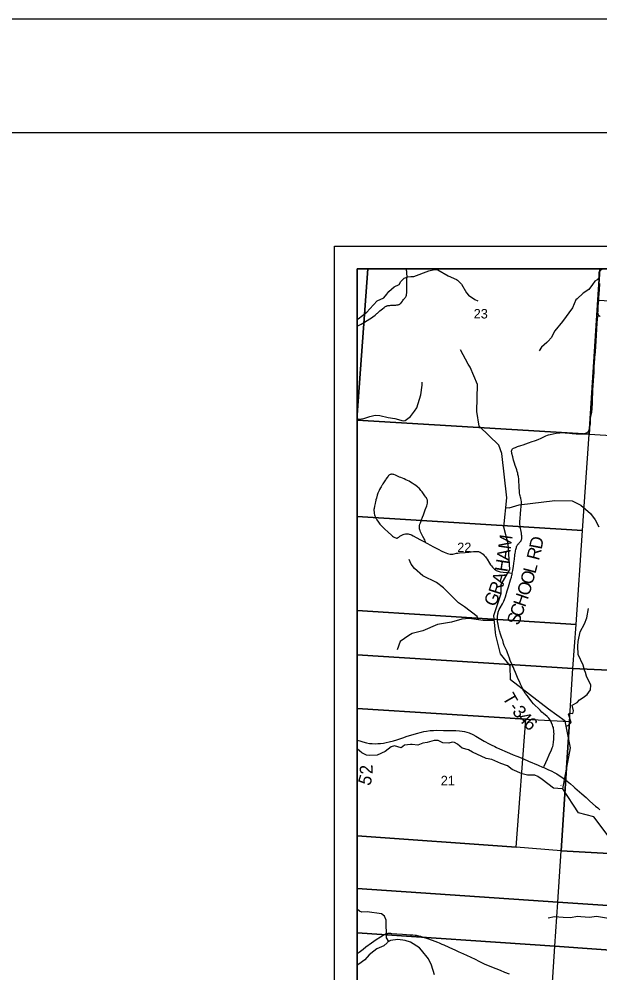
# Model space of a CAD drawing. Extents: x 0 to 34, y 0 to 22.
# Drawn here: x 22.027 to 24.586, y 17.797 to 22 of the extents above; entities that cross this region are included whole.
import ezdxf

# ---------------------------------------------------------------- set-up
doc = ezdxf.new("R2010")
doc.units = 0
for name, color, linetype in [('Default', 7, 'Continuous'), ('GM_X_County_Road', 7, 'Continuous'), ('GM_X_Minor_River', 7, 'Continuous'), ('GM_X_Section', 7, 'Continuous'), ('GM_X_Section_Text', 7, 'Continuous'), ('GM_X_State_Route', 7, 'Continuous'), ('GM_X_Township_Road', 7, 'Continuous'), ('GM_X_Township_Road_Text', 7, 'Continuous'), ('SH_Border', 7, 'Continuous'), ('SH_Cut_Line', 7, 'Continuous'), ('SH_Data', 7, 'Continuous'), ('SH_Text', 7, 'Continuous')]:
    doc.layers.add(name, color=color, linetype=linetype)

msp = doc.modelspace()

# ---------------------------------------------------------------- linework, layer by layer
at = {"layer": 'Default'}
for points in [[(23.5639, 20.9), (23.5167, 20.9), (23.5167, 20.2565)], [(23.5167, 20.2565), (23.5167, 20.233), (24.5388, 20.1708), (24.5856, 20.9), (23.5639, 20.9)], [(25.6226, 20.9), (24.5856, 20.9), (24.5388, 20.1708), (25.5703, 20.1097)], [(23.5167, 20.233), (23.5167, 19.8081), (24.5096, 19.7459), (24.5388, 20.1708)], [(23.5167, 19.8081), (23.5167, 19.3932), (24.4804, 19.3317), (24.5096, 19.7459)], [(23.5167, 19.3932), (23.5167, 19.1986), (24.4668, 19.1382), (24.4804, 19.3317)], [(23.5167, 19.1986), (23.5167, 18.962), (24.259, 18.9151), (24.4515, 18.9043), (24.4668, 19.1382)], [(23.5167, 18.962), (23.5167, 18.4005), (24.2171, 18.351), (24.259, 18.9151)], [(23.5167, 18.4005), (23.5167, 18.1686), (24.3998, 18.1092), (24.4145, 18.3347), (24.2171, 18.351)], [(23.5167, 18.1686), (23.5167, 17.973), (24.3871, 17.9146), (24.3998, 18.1092)], [(23.5167, 17.973), (23.5167, 17.5604), (24.3605, 17.505), (24.3871, 17.9146)]]:
    msp.add_lwpolyline(points, close=True, dxfattribs=at)
msp.add_lwpolyline([(27.7198, 20.9), (23.5167, 20.9), (23.5167, 16.1239), (23.5888, 16.1195), (25.0535, 16.0331), (25.3458, 16.0191), (26.0811, 15.9921), (26.3691, 15.9829), (26.8773, 15.953), (26.8866, 15.9536), (26.8953, 15.9537)], dxfattribs=at)
at = {"layer": 'GM_X_County_Road'}
for points in [[(24.5862, 20.6897), (24.5846, 20.6906), (24.5832, 20.6915), (24.5816, 20.693), (24.5804, 20.6944), (24.5789, 20.6969), (24.5782, 20.6985), (24.5776, 20.7002), (24.5774, 20.702), (24.5771, 20.7056), (24.5773, 20.7124), (24.5787, 20.7353), (24.5806, 20.7609), (24.5815, 20.7731), (24.5838, 20.8068), (24.5857, 20.8348)], [(23.5167, 17.8817), (23.5251, 17.8884), (23.5423, 17.9017), (23.5552, 17.9114), (23.5799, 17.9292), (23.6003, 17.9433), (23.6188, 17.9559), (23.6261, 17.9606), (23.632, 17.9643), (23.6365, 17.9667), (23.6391, 17.9679), (23.6415, 17.9688), (23.6452, 17.97), (23.6476, 17.9706), (23.6497, 17.9709), (23.6515, 17.9711), (23.6532, 17.9713), (23.6551, 17.9714), (23.6579, 17.9715), (23.659, 17.9715), (23.6636, 17.9713), (23.6671, 17.9711), (23.7161, 17.9679), (23.752, 17.9653), (23.761, 17.9645), (23.7717, 17.9634), (23.7761, 17.9627), (23.7811, 17.9618), (23.7884, 17.9601), (23.7956, 17.9581), (23.8028, 17.9559), (23.8257, 17.948), (23.8462, 17.9407), (23.8708, 17.9319), (23.8771, 17.9295), (23.8835, 17.9268), (23.8899, 17.924), (23.8977, 17.9204), (23.9202, 17.9099), (23.9502, 17.8963), (23.9641, 17.8899), (23.9722, 17.8862), (23.9974, 17.8748), (24.0165, 17.866), (24.0364, 17.8569), (24.053, 17.8487), (24.0669, 17.8417), (24.0765, 17.8373), (24.0941, 17.8297), (24.1278, 17.8158), (24.1458, 17.8085), (24.1653, 17.8003), (24.1861, 17.7921)]]:
    msp.add_lwpolyline(points, dxfattribs=at)
at = {"layer": 'GM_X_Minor_River'}
for points in [[(23.5167, 20.6785), (23.5205, 20.6796), (23.5588, 20.709), (23.5724, 20.7238), (23.605, 20.7581), (23.6331, 20.771), (23.6475, 20.7885), (23.6558, 20.7999), (23.6794, 20.8205), (23.701, 20.8308), (23.7089, 20.8437), (23.723, 20.8578), (23.7389, 20.8639), (23.7533, 20.8654), (23.7665, 20.8655), (23.8325, 20.8899), (23.8564, 20.896), (23.8719, 20.8952), (23.9174, 20.8687), (23.9542, 20.852), (23.9587, 20.8493), (23.9754, 20.8322), (23.9978, 20.7931), (24.0065, 20.7836), (24.0349, 20.7646), (24.0478, 20.7582)], [(24.6012, 20.9), (24.5899, 20.8956), (24.5812, 20.8846), (24.5808, 20.8599), (24.5732, 20.8511), (24.5626, 20.845), (24.5535, 20.831), (24.5372, 20.8089), (24.5118, 20.7921), (24.486, 20.7666), (24.4792, 20.7628), (24.4651, 20.7282), (24.4211, 20.6669), (24.3878, 20.6262), (24.3703, 20.595), (24.3574, 20.581), (24.3517, 20.5745), (24.3286, 20.5539), (24.3187, 20.5383)], [(24.6358, 18.3825), (24.5593, 18.4839), (24.4908, 18.5019), (24.4222, 18.6075), (24.4559, 18.7885), (24.4331, 18.9063), (24.3595, 18.9584), (24.1919, 19.0886), (24.1907, 19.1496), (24.1471, 19.2028), (24.1267, 19.2853), (24.1254, 19.2967), (24.1179, 19.3714), (24.1501, 19.4688), (24.1503, 19.509), (24.1885, 19.5747), (24.181, 19.6869), (24.1618, 19.7604), (24.176, 19.8899), (24.1541, 20.0852), (24.1411, 20.123), (24.0538, 20.2057), (24.0442, 20.2713), (24.0457, 20.389), (24.0139, 20.4654), (24.0046, 20.4797), (23.9712, 20.5432)], [(23.5167, 20.2402), (23.5237, 20.2375), (23.5453, 20.2394), (23.5726, 20.2489), (23.5958, 20.2547), (23.6166, 20.2536), (23.653, 20.2437), (23.6829, 20.2392), (23.7197, 20.2301), (23.7284, 20.2309), (23.7508, 20.2491), (23.7682, 20.2727), (23.7785, 20.2876), (23.7971, 20.3446), (23.8024, 20.3868), (23.8028, 20.3933), (23.8032, 20.3994)], [(24.1714, 19.8482), (24.1859, 19.8466), (24.2306, 19.8601), (24.3866, 19.8788), (24.4633, 19.8774), (24.5014, 19.8583), (24.5442, 19.8216), (24.5647, 19.794), (24.5809, 19.763)], [(24.051, 19.3533), (24.0454, 19.3667), (23.9894, 19.4104), (23.962, 19.4275), (23.896, 19.493), (23.8656, 19.5177), (23.8052, 19.5467), (23.7689, 19.5783), (23.7543, 19.5979), (23.7455, 19.6182)], [(24.4383, 18.8844), (24.4478, 18.8886), (24.4584, 18.9), (24.4467, 18.9376), (24.4516, 18.9418), (24.466, 18.9395), (24.4698, 18.9517), (24.4634, 18.976), (24.4854, 18.9882), (24.4952, 19.0004), (24.5119, 19.0107), (24.529, 19.0232), (24.5449, 19.0449), (24.5457, 19.0654), (24.5267, 19.1038), (24.5218, 19.1202), (24.5173, 19.1304), (24.5116, 19.1525), (24.4904, 19.2), (24.4881, 19.2361), (24.4904, 19.2566), (24.4984, 19.2996), (24.5185, 19.3349), (24.5283, 19.3619), (24.5356, 19.403)], [(24.1201, 19.3497), (24.0718, 19.3504), (24.0092, 19.3592), (23.9777, 19.3559), (23.9323, 19.342), (23.8706, 19.3322), (23.806, 19.3046), (23.758, 19.2927), (23.7434, 19.283), (23.7054, 19.257), (23.6928, 19.221)], [(24.085, 18.7418), (24.0244, 18.7691), (24.0065, 18.7805), (23.9793, 18.7877), (23.958, 18.8044), (23.9455, 18.8127), (23.9353, 18.8135), (23.9205, 18.8096), (23.8936, 18.8111), (23.8727, 18.8206), (23.8549, 18.821), (23.825, 18.8114), (23.806, 18.8099), (23.7829, 18.8007), (23.7579, 18.8026), (23.7514, 18.8037), (23.7245, 18.8003), (23.7109, 18.7885), (23.6809, 18.7968), (23.6665, 18.793), (23.6396, 18.7724), (23.6043, 18.7561), (23.5721, 18.7553), (23.5581, 18.7556), (23.5373, 18.7659), (23.5167, 18.7845)], [(24.42, 18.6081), (24.3814, 18.6102), (24.331, 18.6485), (24.3116, 18.6626), (24.2995, 18.6675), (24.2673, 18.6679), (24.2434, 18.6743), (24.1991, 18.6929), (24.1779, 18.7096), (24.149, 18.7194), (24.1093, 18.7365), (24.085, 18.7418)], [(24.4132, 18.6247), (24.4144, 18.6225)], [(23.6562, 17.9355), (23.6458, 17.952), (23.6443, 18.0288), (23.6374, 18.047), (23.623, 18.0569), (23.5597, 18.0652), (23.5374, 18.0648), (23.5268, 18.0693), (23.5169, 18.0781), (23.5167, 18.0792)], [(25.0835, 17.7983), (25.0376, 17.8285), (25.0069, 17.8501), (24.9869, 17.8627), (24.9698, 17.8645), (24.9562, 17.8737), (24.9376, 17.8961), (24.8728, 17.9401), (24.8489, 17.9538), (24.7996, 17.9689), (24.7769, 17.9795), (24.7561, 18), (24.7284, 18.0107), (24.6954, 18.0239), (24.6461, 18.0322), (24.6416, 18.033), (24.5711, 18.0455), (24.54, 18.0409), (24.5021, 18.0446), (24.4869, 18.0457), (24.4562, 18.0396), (24.424, 18.0415), (24.3853, 18.0434), (24.3577, 18.0384)], [(23.8568, 17.7876), (23.8436, 17.831), (23.8299, 17.8587), (23.8, 17.8971), (23.7902, 17.9069), (23.7507, 17.9324), (23.7276, 17.9403), (23.695, 17.9445), (23.6628, 17.9391), (23.6503, 17.9322), (23.6492, 17.9288), (23.6344, 17.9155), (23.6037, 17.9033), (23.5904, 17.8923), (23.5695, 17.8759), (23.5506, 17.8549), (23.524, 17.8348), (23.5167, 17.8313)]]:
    msp.add_lwpolyline(points, dxfattribs=at)
at = {"layer": 'GM_X_Section'}
for points in [[(24.5388, 20.1708), (25.5703, 20.1097), (25.5433, 19.6923), (25.5164, 19.2759), (25.5041, 19.0909), (25.5038, 19.0874), (24.9075, 19.1174), (24.4668, 19.1382), (24.4804, 19.3317), (24.5096, 19.7459)], [(24.4668, 19.1382), (24.9075, 19.1174), (24.8626, 18.3102), (24.4145, 18.3347), (24.4515, 18.9043)], [(24.4515, 18.9043), (24.4145, 18.3347), (24.2171, 18.351), (24.259, 18.9151)], [(24.8626, 18.3102), (25.3836, 18.2803), (25.3665, 18.0434), (24.3998, 18.1092), (24.4145, 18.3347)], [(24.3998, 18.1092), (25.3665, 18.0434), (25.4369, 18.0387), (25.4267, 17.8394), (24.3871, 17.9146)], [(25.4267, 17.8394), (25.3999, 17.4262), (24.3605, 17.505), (24.3871, 17.9146)]]:
    msp.add_lwpolyline(points, close=True, dxfattribs=at)
at = {"layer": 'GM_X_State_Route'}
for points in [[(23.5167, 18.823), (23.5274, 18.819), (23.541, 18.8146), (23.5569, 18.8109), (23.5709, 18.8084), (23.5819, 18.8075), (23.5968, 18.8068), (23.6068, 18.807), (23.6187, 18.8077), (23.6317, 18.8092), (23.6446, 18.8115), (23.6579, 18.8145), (23.6759, 18.8196), (23.6908, 18.8242), (23.7214, 18.8345), (23.732, 18.8379), (23.7778, 18.8517), (23.7993, 18.8578), (23.8095, 18.8603), (23.8217, 18.8623), (23.8377, 18.8643), (23.8525, 18.8654), (23.868, 18.8659), (23.8966, 18.8657), (23.927, 18.8654), (23.9512, 18.8647), (23.9667, 18.8638), (23.979, 18.8624), (23.9887, 18.8607), (23.9988, 18.8581), (24.0099, 18.8543), (24.0254, 18.8479), (24.0385, 18.8403), (24.0616, 18.827), (24.0754, 18.8187), (24.0821, 18.8148), (24.0918, 18.8093), (24.1067, 18.8017), (24.1221, 18.7942), (24.13, 18.7906), (24.1439, 18.7845), (24.1768, 18.7702), (24.187, 18.7657), (24.2042, 18.7585), (24.2192, 18.7523), (24.2312, 18.7473), (24.2485, 18.7396), (24.2708, 18.7302), (24.3131, 18.7122), (24.3325, 18.704), (24.338, 18.7016), (24.3591, 18.692), (24.3709, 18.6866), (24.3865, 18.6788), (24.3956, 18.6737), (24.4067, 18.6669), (24.4176, 18.6598), (24.4297, 18.6512), (24.4415, 18.6421), (24.4492, 18.6358), (24.4558, 18.6302), (24.4692, 18.6184), (24.4759, 18.6125)], [(24.4759, 18.6125), (24.4856, 18.604), (24.5053, 18.5865), (24.5248, 18.5693), (24.5415, 18.5543), (24.5665, 18.5321), (24.5762, 18.5236), (24.5839, 18.5175), (24.586, 18.5156)]]:
    msp.add_lwpolyline(points, dxfattribs=at)
at = {"layer": 'GM_X_Township_Road'}
for points in [[(23.5167, 20.6466), (23.5187, 20.6476), (23.5346, 20.6561), (23.5482, 20.6637), (23.5605, 20.671), (23.572, 20.6785), (23.5802, 20.6841), (23.586, 20.6886), (23.5952, 20.6957), (23.5987, 20.6987), (23.6032, 20.7024), (23.6059, 20.7047), (23.6167, 20.7139), (23.6274, 20.7225), (23.6346, 20.7284), (23.6386, 20.7313), (23.6416, 20.7332), (23.6435, 20.7343), (23.6458, 20.7353), (23.6472, 20.7359), (23.649, 20.7364), (23.6513, 20.7371), (23.6533, 20.7376), (23.6556, 20.738), (23.6572, 20.7382), (23.6601, 20.7385), (23.6642, 20.7388), (23.6751, 20.7393), (23.6823, 20.7396), (23.6873, 20.7398), (23.6912, 20.7402), (23.6938, 20.7405), (23.6968, 20.7411), (23.6993, 20.742), (23.7015, 20.7429), (23.7036, 20.7442), (23.7066, 20.7466), (23.7079, 20.7478), (23.7111, 20.7514), (23.7158, 20.7573), (23.718, 20.7601), (23.721, 20.7637), (23.7266, 20.7705), (23.7284, 20.7728), (23.7296, 20.7743), (23.7308, 20.7765), (23.7317, 20.7787), (23.733, 20.7827), (23.7335, 20.7849), (23.7343, 20.7899), (23.7345, 20.7928), (23.7347, 20.798), (23.7347, 20.8002), (23.7346, 20.8073), (23.7352, 20.8337), (23.7358, 20.8572), (23.736, 20.8681), (23.7357, 20.8756), (23.7356, 20.8797), (23.7352, 20.8853), (23.7349, 20.888), (23.7342, 20.8926), (23.7338, 20.8959), (23.7332, 20.8989), (23.733, 20.9)], [(24.5806, 20.7609), (24.6039, 20.7593), (24.6237, 20.7583), (24.6678, 20.7556), (24.7203, 20.7527)], [(24.1973, 20.0991), (24.1977, 20.1006), (24.1983, 20.102), (24.1993, 20.1037), (24.2008, 20.1055), (24.2026, 20.107), (24.2052, 20.1086), (24.2092, 20.1105), (24.2143, 20.1128), (24.2232, 20.1159), (24.2367, 20.1203), (24.2479, 20.1241), (24.2712, 20.1326), (24.2874, 20.1382), (24.2969, 20.1412), (24.3068, 20.1447), (24.316, 20.1483), (24.3245, 20.1521), (24.3476, 20.1629), (24.3545, 20.1658), (24.3598, 20.1676), (24.367, 20.1694), (24.3796, 20.1722), (24.393, 20.1746), (24.4022, 20.1762), (24.4098, 20.1773), (24.4138, 20.1775), (24.417, 20.1776), (24.4232, 20.1775), (24.4332, 20.1768), (24.4511, 20.1752), (24.4629, 20.174), (24.4666, 20.1736), (24.4814, 20.1724), (24.4913, 20.1719), (24.4999, 20.172), (24.5073, 20.1723), (24.5123, 20.1728), (24.5177, 20.1737), (24.5225, 20.175), (24.5259, 20.1763), (24.5292, 20.1779), (24.5317, 20.1798), (24.5333, 20.1814), (24.5357, 20.1847), (24.5369, 20.1874), (24.5377, 20.1896), (24.5392, 20.1949), (24.5417, 20.2051), (24.5431, 20.2117), (24.5436, 20.2153), (24.5439, 20.22), (24.544, 20.225), (24.544, 20.2307), (24.544, 20.2332), (24.5442, 20.2356), (24.5444, 20.2385), (24.5449, 20.2415), (24.5464, 20.2487), (24.5476, 20.2549), (24.5486, 20.2606), (24.5497, 20.2685), (24.5512, 20.2818), (24.5519, 20.2928), (24.5524, 20.3008), (24.5527, 20.3112), (24.5531, 20.3229), (24.5536, 20.3359), (24.554, 20.3452), (24.5542, 20.3495), (24.5548, 20.3645), (24.5552, 20.3713), (24.5557, 20.3799), (24.5564, 20.3904), (24.5571, 20.4013), (24.5576, 20.4081), (24.5586, 20.4235), (24.5597, 20.4452), (24.5607, 20.4638), (24.5623, 20.4892), (24.5629, 20.4985), (24.5634, 20.5059), (24.5637, 20.5102), (24.5642, 20.5183), (24.5655, 20.535), (24.5688, 20.5802), (24.5724, 20.6348), (24.5742, 20.6583), (24.5756, 20.6801), (24.5762, 20.6858), (24.577, 20.6887), (24.5783, 20.691), (24.5804, 20.6944)], [(24.338, 18.7016), (24.3406, 18.708), (24.3471, 18.7234), (24.3545, 18.7405), (24.3619, 18.7576), (24.3717, 18.7791), (24.3758, 18.7888), (24.378, 18.7952), (24.3793, 18.8), (24.3802, 18.8048), (24.3809, 18.8109), (24.3822, 18.8295), (24.3832, 18.8425), (24.3835, 18.8505), (24.3833, 18.858), (24.3827, 18.866), (24.3819, 18.8721), (24.3806, 18.8775), (24.3787, 18.8833), (24.3764, 18.8891), (24.372, 18.8994), (24.3691, 18.9055), (24.3665, 18.9104), (24.3634, 18.915), (24.3604, 18.9189), (24.3571, 18.9225), (24.3526, 18.9267), (24.3368, 18.9399), (24.3303, 18.9456), (24.3218, 18.9539), (24.3131, 18.9627), (24.3006, 18.9757), (24.2938, 18.983), (24.2862, 18.992), (24.2702, 19.0127), (24.2648, 19.0195), (24.258, 19.0283), (24.2559, 19.0313), (24.2516, 19.0373), (24.2501, 19.0394), (24.2474, 19.0442), (24.2425, 19.0543), (24.2356, 19.0697), (24.231, 19.0803), (24.2262, 19.091), (24.2199, 19.1057), (24.2136, 19.1213), (24.2086, 19.1334), (24.2049, 19.1419), (24.201, 19.1503), (24.1986, 19.1554), (24.1934, 19.1667), (24.1903, 19.1741), (24.1867, 19.1834), (24.1825, 19.1951), (24.1783, 19.2072), (24.1751, 19.2154), (24.1684, 19.2301), (24.1645, 19.2393), (24.1614, 19.2487), (24.1573, 19.2624), (24.1538, 19.2723), (24.1509, 19.2805), (24.1483, 19.2888), (24.1439, 19.3037), (24.1408, 19.3163), (24.1393, 19.323), (24.1371, 19.3338), (24.1352, 19.3441), (24.1343, 19.3516), (24.134, 19.3561), (24.1339, 19.3614), (24.1346, 19.3688), (24.1356, 19.3769), (24.1361, 19.3793), (24.1368, 19.3828), (24.1377, 19.3859), (24.1389, 19.3907), (24.1403, 19.3944), (24.1422, 19.3976), (24.1465, 19.4049), (24.157, 19.4239), (24.1611, 19.4322), (24.1623, 19.435), (24.1652, 19.4425), (24.1691, 19.4542), (24.177, 19.4804), (24.1827, 19.4988), (24.1924, 19.5283), (24.1959, 19.5402), (24.1982, 19.5492), (24.1988, 19.5523), (24.1998, 19.5582), (24.202, 19.5708), (24.2048, 19.5886), (24.2084, 19.6123), (24.2091, 19.6179), (24.2098, 19.6241), (24.2107, 19.6333), (24.2115, 19.6397), (24.2125, 19.6466), (24.2134, 19.6525), (24.2141, 19.6573), (24.2152, 19.6632), (24.2163, 19.6676), (24.2175, 19.6721), (24.2185, 19.6752), (24.2195, 19.6775), (24.221, 19.6807), (24.2224, 19.6831), (24.2239, 19.6854), (24.2278, 19.6897), (24.2295, 19.6916), (24.2341, 19.6958), (24.2365, 19.6985), (24.2382, 19.701), (24.2392, 19.7031), (24.24, 19.7049), (24.2405, 19.7066), (24.241, 19.7095), (24.2413, 19.7131), (24.2414, 19.7158), (24.2415, 19.7192), (24.2413, 19.7224), (24.2407, 19.7278), (24.2396, 19.7339), (24.2381, 19.7418), (24.2366, 19.7491), (24.2354, 19.7552), (24.2345, 19.7601), (24.2337, 19.7675), (24.2334, 19.7731), (24.2334, 19.7764), (24.2334, 19.7794), (24.2336, 19.7862), (24.2344, 19.7985), (24.2347, 19.8041), (24.2357, 19.8148), (24.2365, 19.8226), (24.2379, 19.8362), (24.2394, 19.8529), (24.24, 19.8635), (24.24, 19.8684), (24.2397, 19.8739), (24.2387, 19.8806), (24.2368, 19.889), (24.2358, 19.8932), (24.2347, 19.8987), (24.2335, 19.9042), (24.2321, 19.9128), (24.231, 19.922), (24.2301, 19.9332), (24.2296, 19.9463), (24.2292, 19.9605), (24.2289, 19.9655), (24.2286, 19.9706), (24.2281, 19.9753), (24.2272, 19.9807), (24.2265, 19.9846), (24.2256, 19.9893), (24.2246, 19.9938), (24.2234, 19.9987), (24.2214, 20.007), (24.2196, 20.0134), (24.218, 20.0183), (24.2129, 20.033), (24.2096, 20.043), (24.2056, 20.0561), (24.2015, 20.0711), (24.1978, 20.0862), (24.1972, 20.0899), (24.1969, 20.0931), (24.1967, 20.095), (24.1968, 20.0971), (24.1973, 20.0991)], [(23.8172, 19.694), (23.8167, 19.6958), (23.8155, 19.7), (23.8137, 19.7047), (23.8111, 19.7103), (23.8059, 19.7202), (23.7987, 19.7339), (23.7954, 19.7406), (23.7934, 19.7458), (23.7923, 19.7494), (23.7915, 19.753), (23.7909, 19.7579), (23.7909, 19.7629), (23.7913, 19.766), (23.7916, 19.7684), (23.7929, 19.7739), (23.7949, 19.7804), (23.7992, 19.7927), (23.8038, 19.8049), (23.8081, 19.8159), (23.8114, 19.8246), (23.8159, 19.8368), (23.8229, 19.8548), (23.8251, 19.8613), (23.8264, 19.8667), (23.8269, 19.871), (23.8268, 19.8754), (23.8265, 19.8778), (23.826, 19.8803), (23.825, 19.8832), (23.8233, 19.8865), (23.8215, 19.8897), (23.8187, 19.8938), (23.8151, 19.8989), (23.8122, 19.9029), (23.802, 19.917), (23.7975, 19.9229), (23.7942, 19.9267), (23.7903, 19.9307), (23.7867, 19.934), (23.7829, 19.9373), (23.7742, 19.9442), (23.7677, 19.9491), (23.759, 19.955), (23.7557, 19.9568), (23.7448, 19.9631), (23.7312, 19.97), (23.7228, 19.9739), (23.716, 19.9768), (23.7085, 19.9798), (23.7033, 19.9819), (23.6852, 19.99), (23.6782, 19.9925), (23.6746, 19.9934), (23.6709, 19.9939), (23.6672, 19.9939), (23.6641, 19.9935), (23.6618, 19.9928), (23.6595, 19.9917), (23.657, 19.99), (23.6546, 19.988), (23.6522, 19.9853), (23.6486, 19.9803), (23.6433, 19.9728), (23.6412, 19.9698), (23.6297, 19.9523), (23.6261, 19.9467), (23.6249, 19.9445), (23.622, 19.9391), (23.6193, 19.9344), (23.6152, 19.9269), (23.6127, 19.9221), (23.6117, 19.92), (23.6081, 19.9115), (23.605, 19.9022), (23.601, 19.8881), (23.5992, 19.8815), (23.5979, 19.8768), (23.5973, 19.8744), (23.5955, 19.8659), (23.5925, 19.8535), (23.5905, 19.8431), (23.59, 19.8389), (23.59, 19.834), (23.5905, 19.8267), (23.5913, 19.8206), (23.5927, 19.8147), (23.5939, 19.8106), (23.595, 19.8077), (23.5968, 19.8038), (23.5994, 19.7989), (23.6034, 19.7927), (23.6104, 19.7832), (23.6168, 19.7749), (23.6225, 19.7685), (23.6312, 19.7597), (23.6387, 19.7523), (23.6517, 19.7402), (23.6687, 19.7243), (23.6725, 19.7212), (23.6771, 19.7181), (23.6819, 19.7154), (23.6863, 19.7133), (23.6892, 19.7123), (23.6905, 19.7121), (23.6921, 19.7122), (23.6933, 19.7127), (23.6944, 19.7134), (23.6993, 19.7173), (23.7048, 19.7213), (23.7101, 19.7246), (23.7156, 19.7275), (23.7196, 19.7291), (23.7238, 19.7305), (23.7287, 19.7315), (23.7336, 19.7319), (23.7373, 19.7317), (23.7417, 19.7312), (23.7459, 19.7302), (23.7507, 19.7287), (23.7558, 19.7266), (23.7625, 19.7232), (23.7768, 19.7156), (23.796, 19.7053), (23.8152, 19.695), (23.8172, 19.694), (23.8231, 19.6908), (23.8394, 19.6817), (23.8503, 19.6757), (23.8733, 19.6635), (23.8887, 19.6556), (23.8994, 19.6506), (23.9075, 19.6472), (23.914, 19.645), (23.9201, 19.6434), (23.9262, 19.6423), (23.9325, 19.6418), (23.9375, 19.6422), (23.9442, 19.6436), (23.9544, 19.6461), (23.9593, 19.6469), (23.9672, 19.6479), (23.9923, 19.65), (24.0076, 19.6514), (24.0284, 19.6534), (24.0388, 19.6541), (24.0455, 19.6541), (24.0503, 19.6535), (24.0544, 19.6524), (24.0584, 19.6509), (24.0626, 19.6486), (24.067, 19.6454), (24.0711, 19.6418), (24.0763, 19.6366), (24.0811, 19.631), (24.0852, 19.6257), (24.0886, 19.6206), (24.0993, 19.6027), (24.104, 19.5954), (24.108, 19.5899), (24.1128, 19.5842), (24.1171, 19.5798), (24.1212, 19.5761), (24.1256, 19.5727), (24.1288, 19.5707), (24.1327, 19.5688), (24.1368, 19.5673), (24.1415, 19.566), (24.147, 19.5649), (24.1598, 19.5631), (24.1775, 19.5609), (24.1885, 19.5596), (24.1998, 19.5582)]]:
    msp.add_lwpolyline(points, dxfattribs=at)
at = {"layer": 'SH_Border'}
msp.add_lwpolyline([(1.5, 21.5), (33.5, 21.5), (33.5, 0.5), (1.5, 0.5)], close=True, dxfattribs=at)
at = {"layer": 'SH_Cut_Line'}
msp.add_lwpolyline([(0, 0), (34, 0), (34, 22), (0, 22)], close=True, dxfattribs=at)
at = {"layer": 'SH_Data'}
for points in [[(23.4167, 21), (30.4167, 21), (30.4167, 14), (23.4167, 14)], [(23.5167, 20.9), (30.3167, 20.9), (30.3167, 14.1), (23.5167, 14.1)]]:
    msp.add_lwpolyline(points, close=True, dxfattribs=at)
at = {"layer": 'SH_Text'}
msp.add_lwpolyline([(30.3167, 20.9), (23.5167, 20.9), (23.5167, 14.1), (29.5051, 14.1)], dxfattribs=at)

# ---------------------------------------------------------------- texts
at = {"layer": 'GM_X_Section_Text'}
for s, p in [('23', (24.0296, 20.6806)), ('22', (23.9571, 19.6509)), ('21', (23.8846, 18.6234))]:
    msp.add_text(s, height=0.04186, rotation=0, dxfattribs=at).set_placement(p)
at = {"layer": 'GM_X_Township_Road_Text'}
for s, rotation, p in [('M', 81.8979, (24.1928, 19.6608)), ('D', 79.1067, (24.329, 19.6606)), ('R', 75.6263, (24.3166, 19.6117)), ('A', 81.8963, (24.1858, 19.6113)), ('H', 81.2444, (24.1781, 19.5612)), ('L', 75.2987, (24.3013, 19.5533)), ('A', 73.2367, (24.1617, 19.5049)), ('O', 74.8704, (24.2881, 19.5046)), ('R', 71.9795, (24.1469, 19.4592)), ('O', 72.949, (24.2729, 19.4548)), ('G', 64.7106, (24.1226, 19.4067)), ('H', 71.0631, (24.256, 19.4056)), ('C', 70.3553, (24.2401, 19.3609)), ('S', 70.2337, (24.2271, 19.3247)), ('T', 299.8135, (24.1545, 19.0102)), ('-', 308.9568, (24.1812, 18.9652)), ('3', 309.8645, (24.1965, 18.9463)), ('4', 312.7083, (24.221, 18.9171)), ('6', 315.1743, (24.2466, 18.8895)), ('2', 92.7229, (23.5856, 18.6732)), ('5', 72.8422, (23.5726, 18.6185))]:
    msp.add_text(s, height=0.0568, rotation=rotation, dxfattribs=at).set_placement(p)

doc.saveas('drawing.dxf')
